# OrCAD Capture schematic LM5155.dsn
size A
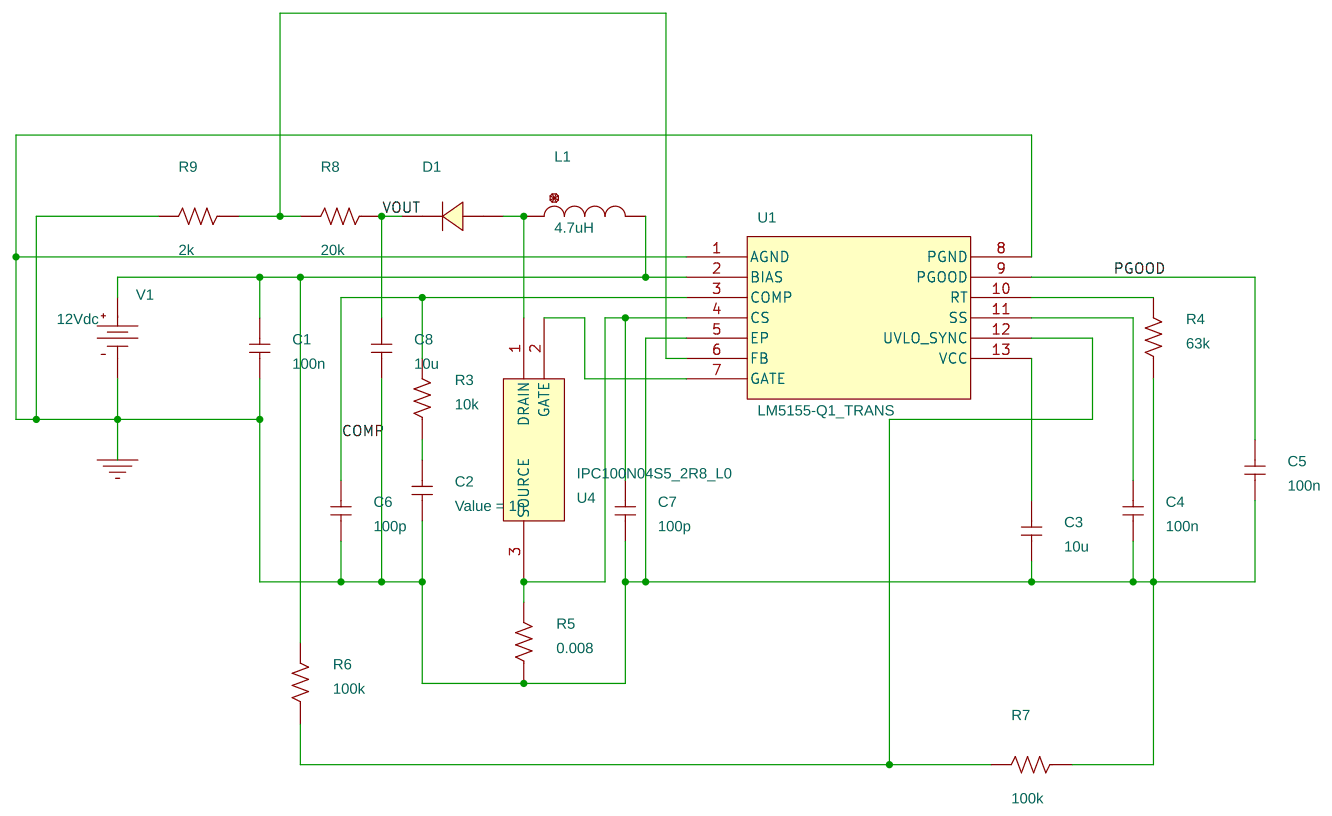
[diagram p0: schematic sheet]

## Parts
C1  100n  [cap196]
C2  1n  [cap196]
C3  10u  [cap196]
C4  100n  [cap196]
C5  100n  [cap196]
C6  100p  [cap196]
C7  100p  [cap196]
C8  10u  [cap196]
D1  16SYQ060C  [DO41]
L1  4.7uH  [DISC350x175LS200x100034]
R3  10k  [AXRC05]
R4  63k  [AXRC05]
R5  0.008  [AXRC05]
R6  100k  [AXRC05]
R7  100k  [AXRC05]
R8  20k  [AXRC05]
R9  2k  [AXRC05]
U1  LM5155-Q1_TRANS
U4  IPC100N04S5_2R8_L0
V1  VDC

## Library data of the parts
C1-C8 = C
D1 = 16SYQ060C
L1 = L
R3-R9 = R
U1 = LM5155-Q1_TRANS
U4 = IPC100N04S5_2R8_L0
V1 = VDC: DC: 12Vdc

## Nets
0: C1.1 C2.1 C3.1 C4.1 C5.1 C6.1 C7.1 C8.1 R4.1 R5.1 R7.1 R9.2 U1.1(AGND) U1.5(EP) U1.8(PGND) V1.1(-)
COMP: C6.2 R3.2 U1.3(COMP)
PGOOD: C5.2 U1.9(PGOOD)
VOUT: C8.2 D1.1(C) R8.1
N14423: C1.2 L1.2 R6.2 U1.2(BIAS) V1.0(+)
N14789: C2.2 R3.1
N15110: R4.2 U1.10(RT)
N15288: R6.1 R7.2 U1.12(UVLO_SYNC)
N15396: C3.2 U1.13(VCC)
N15524: C4.2 U1.11(SS)
N15652: R8.2 R9.1 U1.6(FB)
N16103: U1.7(GATE) U4.2(GATE)
N16117: D1.2(A) L1.1 U4.1(DRAIN)
N16661: C7.2 R5.2 U1.4(CS) U4.3(SOURCE)
